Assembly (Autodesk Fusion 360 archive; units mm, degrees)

design "Assembly" references "Battery", "Screw", "Finger-Joint Box"
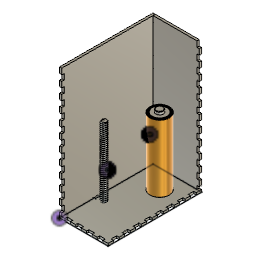
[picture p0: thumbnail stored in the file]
part number: 2025-09-17-23-08-52-484
component_insert "Component Insert1"
component_insert "Component Insert2"
component_insert "Component Insert3"
position "Position1"

design "Screw"
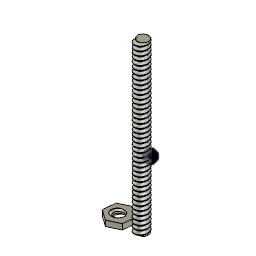
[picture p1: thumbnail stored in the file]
part number: 2025-09-17-21-38-27-805
sketch "Sketch1" plane through (0, 0, 0) normal (0, 0, 1) x axis (1, 0, 0)
  circle C1 centre (0, 0) radius 0.125
  point P1 (0, 0)
  point P2 (0, 0)
  coincident P1 P2
  dimension "d1" diameter C1 = 0.25
extrude "Extrude1" new body sketch "Sketch1" along normal blind 3
thread "Thread1" ThreadOffset 0 ThreadLength 10
sketch "Sketch2" plane through (0, 0, 0) normal (0, 0, 1) x axis (1, 0, 0)
  line L1 (-0.1903, 0.0968) -> (-0.2113, -0.1332)
  line L2 (-0.379, 0.23) -> (-0.1903, 0.0968)
  line L3 (-0.5887, 0.1332) -> (-0.379, 0.23)
  line L4 (-0.6097, -0.0968) -> (-0.5887, 0.1332)
  line L5 (-0.421, -0.23) -> (-0.6097, -0.0968)
  line L6 (-0.2113, -0.1332) -> (-0.421, -0.23)
  circle C1 centre (-0.4, 0) radius 0.125
  point P2 (-0.4, 0)
  point P9 (-0.4, 0)
  coincident P2 P9
  dimension "d6" diameter C1 = 0.25
  dimension "d7" distance P9 L6 = 0.2
extrude "Extrude2" new body sketch "Sketch2" along normal blind 0.1
thread "Thread2" ThreadOffset 0 ThreadLength 10
sketch "Sketch3" plane through (0, 0, 0) normal (0, 0, 1) x axis (1, 0, 0)
scale "Scale1" ScaleFactor 25
scale "Scale2"
scale "Scale3" ScaleFactor 0.5

design "Finger-Joint Box"
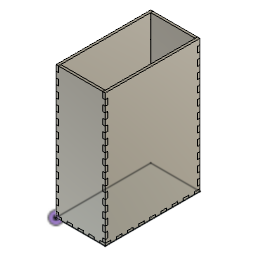
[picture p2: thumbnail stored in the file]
part number: 2025-09-15-00-10-07-891
part number: 2025-09-15-00-12-07-894
parameter "height" = 350
parameter "width" = 130
parameter "length" = 250
parameter "cboard" = 6.3
parameter "lfingerw" = 14.7059 (= "length / ( ( lfingers * 2 ) + 1 )")
parameter "wfingerw" = 14.4444 (= "width / ( ( wfingers * 2 ) + 1 )")
parameter "hfingerw" = 15.2174 (= "height / ( ( hfingers * 2 ) + 1 )")
sketch "bottom panel" plane through (0, 0, 0) normal (0, 0, 1) x axis (1, 0, 0)
  line L1 (130, 0) -> (0, 0)
  line L2 (130, 250) -> (130, 0)
  line L3 (0, 250) -> (130, 250)
  line L4 (0, 0) -> (0, 250)
  point P1 (0, 0)
  point P2 (0, 0)
  point P5 (0, 250)
  point P4 (130, 250)
  horizontal L1
  vertical L2
  horizontal L3
  vertical L4
  coincident P1 P2
  dimension "d30" distance P2 P5 = 250 (= "length")
  dimension "d31" distance P4 P5 = 130 (= "width")
extrude "Extrude4" new body sketch "bottom panel" along normal blind 6.3 (= "cboard") bodies "Bottom Panel"
sketch "bottom fingers" plane through (0, 0, 0) normal (-1, 0, 0) x axis (0, -1, 0)
  line L1 (0, 0) -> (-250, 0)
  line L2 (0, 6.3) -> (0, 0)
  line L3 (-250, 6.3) -> (0, 6.3)
  line L4 (-250, 0) -> (-250, 6.3)
  line L5 (-220.5882, 0) -> (-235.2941, 0)
  line L6 (-220.5882, 6.3) -> (-220.5882, 0)
  line L7 (-235.2941, 6.3) -> (-220.5882, 6.3)
  line L8 (-235.2941, 0) -> (-235.2941, 6.3)
  point P8 (-220.5882, 6.3)
  point P6 (-235.2941, 0)
  point P9 (-235.2941, 6.3)
  horizontal L5
  vertical L6
  horizontal L7
  vertical L8
  coincident L3 P8
  coincident L1 P6
  dimension "d34" distance P8 P9 = 14.7059 (= "lfingerw")
  dimension "d35" distance L4 L8 = 14.7059 (= "lfingerw")
extrude "Extrude5" cut sketch "bottom fingers" profile of L1 L3 L5 L6 L7 L8 no distance stored
rectangular_pattern "R-Pattern2" uSpaceDistance 205.8824 (= "length - ( lfingerw * 3 )") vSpaceDistance 0
sketch "Front Panel Sketch" plane through (0, 0, 0) normal (1, 0, 0) x axis (0, 1, 0)
  line L1 (250, 0) -> (0, 0)
  line L2 (250, 350) -> (250, 0)
  line L3 (0, 350) -> (250, 350)
  line L4 (0, 0) -> (0, 350)
  point P1 (0, 0)
  point P2 (0, 0)
  point P3 (250, 0)
  point P4 (250, 350)
  perpendicular L1 L2
  parallel L1 L3
  parallel L2 L4
  horizontal L1
  coincident P1 P2
  dimension "d42" distance P3 P4 = 350 (= "height")
extrude "Extrude6" new body sketch "Front Panel Sketch" along normal blind 6.3 (= "cboard") bodies "Front Panel"
combine "Combine1"
sketch "front panel right fingers" plane through (0, 0, 0) normal (0, -1, 0) x axis (1, 0, 0)
  line L1 (6.3, 6.3) -> (0, 6.3)
  line L2 (6.3, 350) -> (6.3, 6.3)
  line L3 (0, 350) -> (6.3, 350)
  line L4 (0, 6.3) -> (0, 350)
  line L5 (6.3, 15.2174) -> (0, 15.2174)
  line L6 (6.3, 30.4348) -> (6.3, 15.2174)
  line L7 (0, 30.4348) -> (6.3, 30.4348)
  line L8 (0, 15.2174) -> (0, 30.4348)
  line L9 (130, 0) -> (0, 0)
  point P8 (6.3, 30.4348)
  point P6 (0, 15.2174)
  point P9 (0, 30.4348)
  horizontal L5
  vertical L6
  horizontal L7
  vertical L8
  coincident L2 P8
  coincident L4 P6
  dimension "d45" distance P6 P9 = 15.2174 (= "hfingerw")
  dimension "d46" distance L5 L9 = 15.2174 (= "hfingerw")
extrude "Extrude7" cut sketch "front panel right fingers" profile of L2 L4 L5 L6 L7 L8 no distance stored
rectangular_pattern "R-Pattern3" uSpaceDistance 304.3478 (= "height - ( hfingerw * 3 )") vSpaceDistance 0
combine "Combine3"
extrude "Extrude9" of existing geometry no distance stored bodies "Back Panel"
combine "Combine4"
sketch "left panel sketch" plane through (0, 0, 0) normal (0, 1, 0) x axis (1, 0, 0)
  line L1 (130, 0) -> (0, 0)
  line L2 (130, -350) -> (130, 0)
  line L3 (0, -350) -> (130, -350)
  line L4 (0, 0) -> (0, -350)
  point P1 (0, 0)
  point P2 (0, 0)
  perpendicular L1 L2
  parallel L1 L3
  parallel L2 L4
  horizontal L1
  coincident P1 P2
extrude "Extrude10" new body sketch "left panel sketch" along normal blind 6.3 (= "cboard") bodies "Left Panel"
sketch "bottom panel left fingers" plane through (0, 0, 0) normal (0, -1, 0) x axis (1, 0, 0)
  line L1 (130, 0) -> (0, 0)
  line L2 (130, 6.3) -> (130, 0)
  line L3 (0, 6.3) -> (130, 6.3)
  line L4 (0, 0) -> (0, 6.3)
  line L5 (28.8889, 0) -> (14.4444, 0)
  line L6 (28.8889, 6.3) -> (28.8889, 0)
  line L7 (14.4444, 6.3) -> (28.8889, 6.3)
  line L8 (14.4444, 0) -> (14.4444, 6.3)
  point P8 (28.8889, 6.3)
  point P6 (14.4444, 0)
  point P9 (14.4444, 6.3)
  horizontal L5
  vertical L6
  horizontal L7
  vertical L8
  coincident L3 P8
  coincident L1 P6
  dimension "d61" distance P8 P9 = 14.4444 (= "wfingerw")
  dimension "d62" distance L4 L8 = 14.4444 (= "wfingerw")
extrude "Extrude11" cut sketch "bottom panel left fingers" profile of L1 L3 L5 L6 L7 L8 no distance stored
rectangular_pattern "R-Pattern4" uSpaceDistance -86.6667 (= "-( ( width - wfingerw * 3 ) )") vSpaceDistance 0
combine "Combine5"
extrude "Extrude12" of existing geometry no distance stored bodies "Right Panel"
combine "Combine6"
combine "Combine7"
combine "Combine8"
extrude "Extrude1" new body blind 6.3 (= "cboard") bodies "Bottom Panel"
sketch "Bottom Panel Front Fingers Sketch" plane through (65, 0, 0) normal (1, 0, 0) x axis (0, 1, 0)
  line L1 (125, 0) -> (-125, 0)
  line L2 (125, 6.3) -> (125, 0)
  line L3 (-125, 6.3) -> (125, 6.3)
  line L4 (-125, 0) -> (-125, 6.3)
  line L5 (-95.5882, 0) -> (-110.2941, 0)
  line L6 (-95.5882, 6.3) -> (-95.5882, 0)
  line L7 (-110.2941, 6.3) -> (-95.5882, 6.3)
  line L8 (-110.2941, 0) -> (-110.2941, 6.3)
  point P8 (-95.5882, 6.3)
  point P6 (-110.2941, 0)
  point P9 (-110.2941, 6.3)
  horizontal L5
  vertical L6
  horizontal L7
  vertical L8
  coincident L3 P8
  coincident L1 P6
  dimension "d17" distance P8 P9 = 14.7059 (= "lfingerw")
  dimension "d18" distance L4 L8 = 14.7059 (= "lfingerw")
extrude "Extrude2" cut sketch "Bottom Panel Front Fingers Sketch" profile of L1 L3 L5 L6 L7 L8 no distance stored
rectangular_pattern "R-Pattern1" uSpaceDistance 205.882 vSpaceDistance 0
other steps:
create_component "CreateComponent1"
named bodies: "Bottom Panel", "Front Panel", "Back Panel", "Left Panel", "Right Panel"

design "Battery"
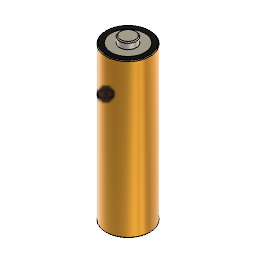
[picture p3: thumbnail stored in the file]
part number: 2025-09-17-21-21-37-963
sketch "Sketch1" plane through (0, 0, 0) normal (0, 0, 1) x axis (1, 0, 0)
  circle C1 centre (0, 0) radius 6.9
  circle C2 centre (0, 0) radius 5.25
  point P1 (0, 0)
  point P2 (0, 0)
  point P3 (0, 0)
  coincident P1 P2
  coincident P1 P3
  dimension "d1" diameter C1 = 13.8
  dimension "d2" diameter C2 = 10.5
extrude "Extrude1" new body sketch "Sketch1" along normal blind 48
extrude "Extrude2" add sketch "Sketch1" profile of C2 against normal blind 0.1
sketch "Sketch2" plane through (0, 0, 48) normal (0, 0, 1) x axis (-1, 0, 0)
  circle C1 centre (0, 0) radius 6.9
  circle C2 centre (0, 0) radius 5.25
  circle C3 centre (0, 0) radius 2.6
  point P1 (0, 0)
  point P3 (0, 0)
  point P4 (0, 0)
  coincident P1 P3
  coincident P1 P4
  dimension "d7" diameter C2 = 10.5
  dimension "d8" diameter C3 = 5.2
extrude "Extrude3" cut sketch "Sketch2" profile of C2 C3 against normal blind 0.01
extrude "Extrude4" add of existing geometry blind 2
fillet "Fillet1" radius 0.3 0.2 0.2
fillet "Fillet2" radius 0.01
sketch "Sketch3" plane through (0, 0, -0.1) normal (0, 0, -1) x axis (1, 0, 0)
  circle C1 centre (0, 0) radius 5.25
move "Move1" RotateAngle 30
move "Move2" RotateAngle 90
scale "Scale1"
scale "Scale2" ScaleFactor 0.75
